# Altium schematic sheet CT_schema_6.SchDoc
size 300 x 177 mm
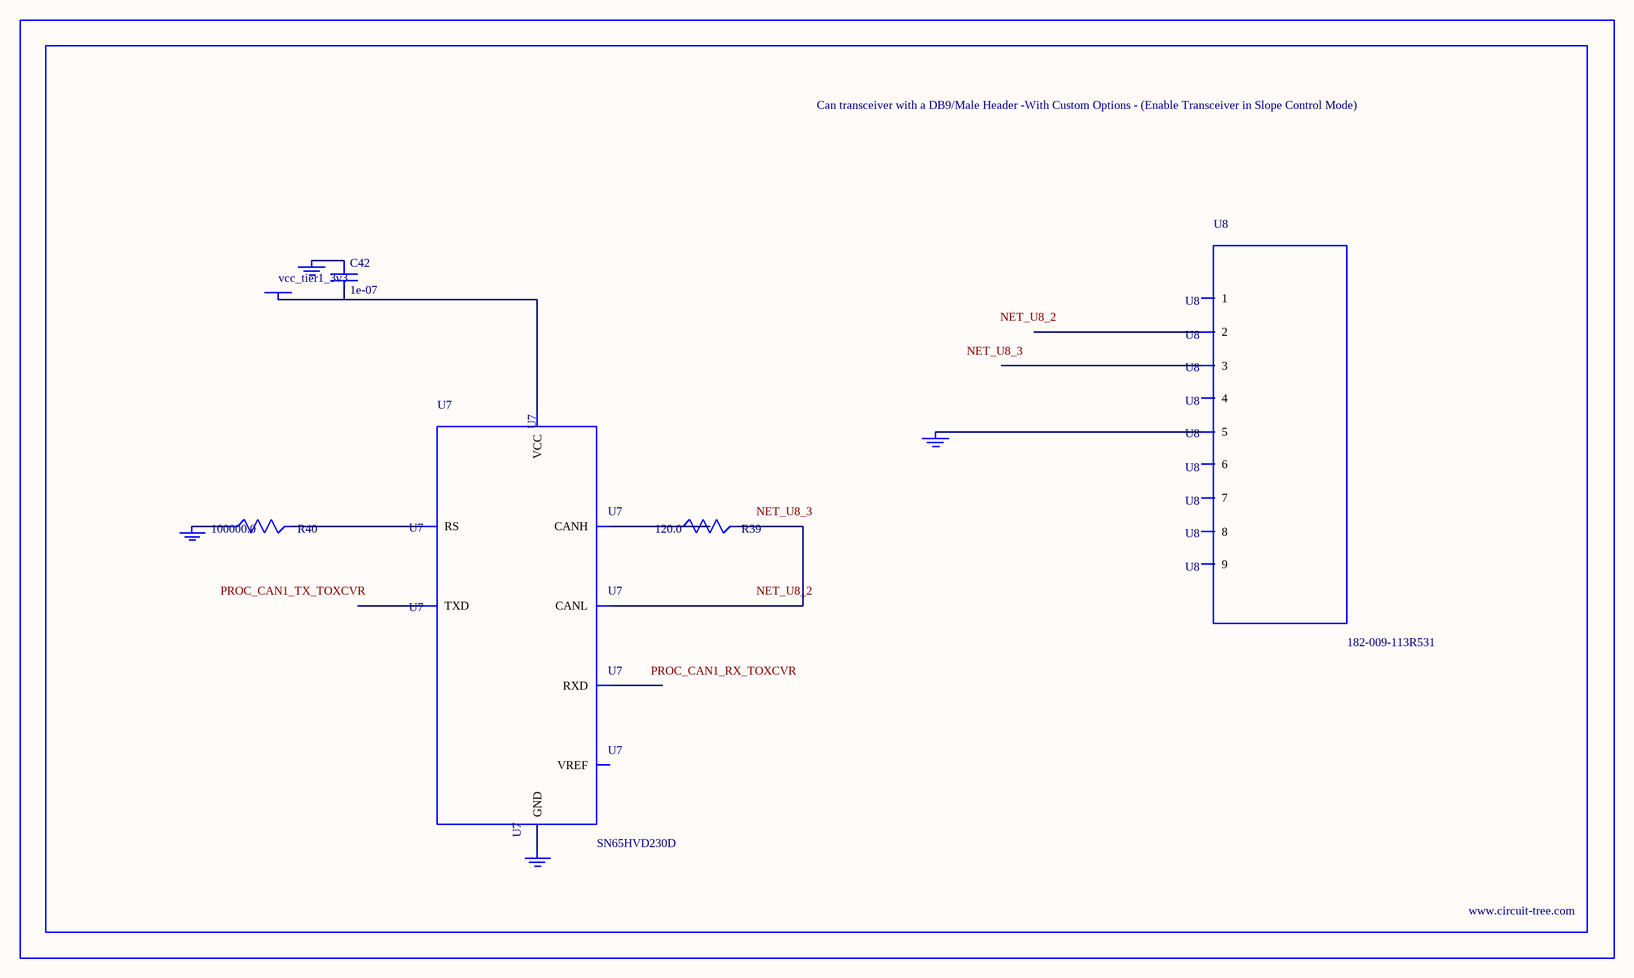
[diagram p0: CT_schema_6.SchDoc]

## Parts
BORDER5  (no value)
C42  1e-07  [C0402]
GND_INSTANCE_5_0  (no value)
GND_INSTANCE_5_1  (no value)
GND_INSTANCE_5_2  (no value)
GND_INSTANCE_5_3  (no value)
POWER_INSTANCE_5_0  vcc_tier1_3v3
R39  120.0  [R0603]
R40  100000.0  [R0603]
U7  SN65HVD230D  [SOIC-8]
U8  182-009-113R531  [182-009-MALE]

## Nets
NetC42_1: C42.1 GND_INSTANCE_5_0.0(GND)
NetC42_2: C42.2 POWER_INSTANCE_5_0.0(PWR) U7.3(VCC)
NetGND_INSTANCE_5_1_0: GND_INSTANCE_5_1.0(GND) R40.1
NetGND_INSTANCE_5_2_0: GND_INSTANCE_5_2.0(GND) U7.2(GND)
NetGND_INSTANCE_5_3_0: GND_INSTANCE_5_3.0(GND) U8.5
NetR39_1: R39.1 U7.7(CANH)
NetR39_2: R39.2 U7.6(CANL)
NetR40_2: R40.2 U7.8(RS)

Not connected (* = marked no-connect by the designer): U7 1(TXD) 4(RXD) 5(VREF); U8 1 2 3 4 6 7 8 9

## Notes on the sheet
- Labels drawn without touching a wire or pin: NET_U8_2, NET_U8_3, PROC_CAN1_RX_TOXCVR, PROC_CAN1_TX_TOXCVR

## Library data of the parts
BORDER5 = BORDER_PAGE5
C42 = C0402C104K3RACTU
GND_INSTANCE_5_0-GND_INSTANCE_5_3 = GND
POWER_INSTANCE_5_0 = PWR
R39 = RC0603JR-07120RL
R40 = RC0603JR-07100KL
